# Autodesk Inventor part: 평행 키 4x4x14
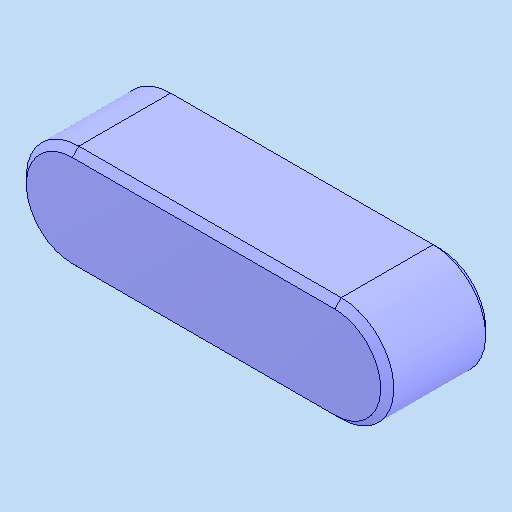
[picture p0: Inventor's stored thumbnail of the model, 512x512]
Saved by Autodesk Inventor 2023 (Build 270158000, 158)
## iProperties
Created: 2026-06
Part Number: 평행 키 4x4x14
Material: 강철, 연강
Description: 키 및 해당 키홈
Document SubType Name: Modeling
Designer: home
Density: 7.85 g/cm^3
Appearance: 기본값
Sending System: Autodesk Inventor 2027
Preprocessor: ST-DEVELOPER v20.1
Author: jhkim
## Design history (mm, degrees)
feature "Solid1"
node "솔리드1"
